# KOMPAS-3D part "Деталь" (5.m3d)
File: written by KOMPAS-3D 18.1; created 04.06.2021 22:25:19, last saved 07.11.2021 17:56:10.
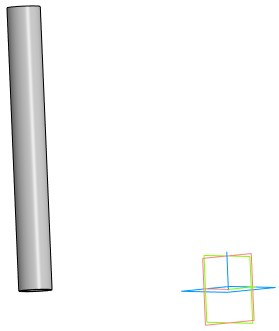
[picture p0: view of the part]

Document properties: Автор: 111; Полное имя файла: C:\Users\admin\Desktop\ffb\5.m3d

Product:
- Part/product: Деталь
    Масса: 0.345327
    source file: ..\10.cdw

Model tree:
1. Эскиз:1
2. Элемент выдавливания:1
     Расстояние 1 = 212
3. Элемент выдавливания:2
     Расстояние 2 = -212
4. Элемент выдавливания:3
     Расстояние 1 = 212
